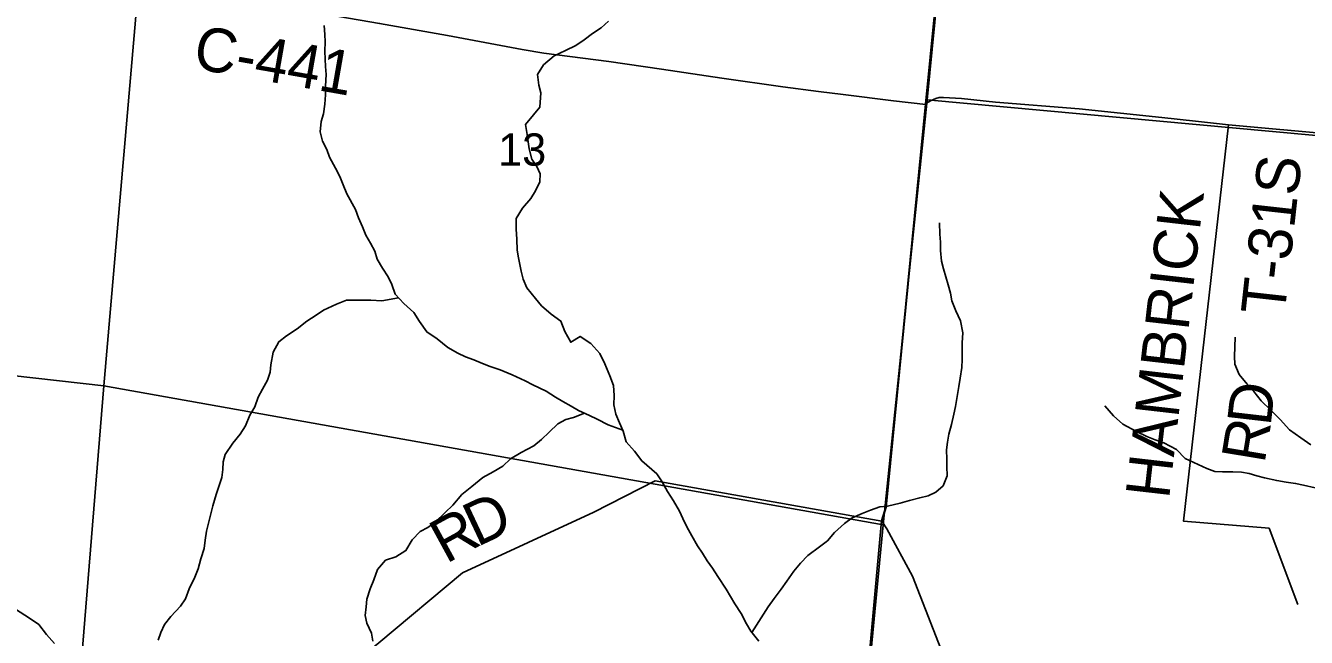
# Model space of a CAD drawing. Extents: x 0 to 42, y 0 to 22.
# Drawn here: x 4.613 to 5.443, y 17.925 to 18.322 of the extents above; entities that cross this region are included whole.
import ezdxf

# ---------------------------------------------------------------- set-up
doc = ezdxf.new("R2010")
doc.units = 0
for name, color, linetype in [('GM_X_County_Road', 7, 'Continuous'), ('GM_X_County_Road_Text', 7, 'Continuous'), ('GM_X_Minor_River', 7, 'Continuous'), ('GM_X_Section', 7, 'Continuous'), ('GM_X_Section_Text', 7, 'Continuous'), ('GM_X_Township', 7, 'Continuous'), ('GM_X_Township_Road', 7, 'Continuous'), ('GM_X_Township_Road_Text', 7, 'Continuous')]:
    doc.layers.add(name, color=color, linetype=linetype)

msp = doc.modelspace()

# ---------------------------------------------------------------- linework, layer by layer
at = {"layer": 'GM_X_County_Road'}
for points in [[(4.81578, 18.32783), (4.84215, 18.32344), (4.88614, 18.31567), (4.93448, 18.30655), (4.94854, 18.30422), (4.99075, 18.29864), (5.0248, 18.29385), (5.0639, 18.28795), (5.10334, 18.28236), (5.1266, 18.27937), (5.14248, 18.27731), (5.17514, 18.27319), (5.19606, 18.27082)], [(4.63561, 17.80179), (4.69832, 17.82776), (4.72485, 17.83901), (4.75732, 17.85441), (4.77317, 17.86587), (4.84161, 17.92186), (4.89586, 17.96725), (4.98086, 18.00667), (5.02064, 18.02691), (5.16751, 18.00075), (5.1704, 18.00991), (5.19606, 18.27082)], [(5.19606, 18.27082), (5.1977, 18.27238), (5.19967, 18.27352), (5.20249, 18.27481), (5.20484, 18.27535), (5.20745, 18.27548), (5.21927, 18.27469), (5.24122, 18.27246), (5.29542, 18.26803), (5.34906, 18.2624)], [(5.34906, 18.2624), (5.37091, 18.26011), (5.39234, 18.25778), (5.59722, 18.2391)]]:
    msp.add_lwpolyline(points, dxfattribs=at)
at = {"layer": 'GM_X_Minor_River'}
for points in [[(4.99971, 18.05981), (4.99035, 18.06327), (4.98319, 18.0669), (4.9781, 18.06939), (4.97112, 18.07245), (4.96622, 18.07531), (4.96094, 18.07837), (4.95604, 18.08123), (4.95001, 18.08505), (4.94134, 18.08926), (4.93643, 18.09174), (4.92814, 18.09576), (4.92021, 18.09883), (4.9138, 18.10113), (4.9089, 18.10305), (4.90324, 18.10535), (4.89777, 18.10727), (4.89286, 18.10975), (4.88627, 18.11338), (4.87949, 18.11891), (4.87271, 18.12349), (4.86801, 18.13014), (4.86426, 18.13603), (4.85786, 18.14194), (4.85221, 18.14784), (4.85016, 18.1541), (4.84773, 18.15923), (4.84397, 18.16474), (4.8406, 18.17063), (4.83911, 18.17576), (4.8363, 18.18108), (4.8333, 18.18621), (4.83105, 18.19152), (4.82843, 18.19741), (4.82657, 18.20273), (4.82094, 18.21299), (4.81851, 18.21887), (4.81627, 18.22419), (4.81364, 18.22951), (4.80971, 18.23673), (4.80803, 18.24166), (4.80522, 18.24717), (4.80373, 18.25305), (4.80433, 18.25988), (4.80586, 18.2648), (4.80664, 18.27105), (4.80705, 18.27711), (4.80707, 18.2828), (4.80748, 18.29038), (4.80713, 18.2955), (4.80677, 18.30024), (4.8066, 18.30535), (4.80682, 18.31142), (4.80665, 18.31616), (4.8063, 18.32204)], [(5.08781, 17.92296), (5.08274, 17.92943), (5.07992, 17.93437), (5.07636, 17.94102), (5.07242, 17.94729), (5.06679, 17.9568), (5.06135, 17.96497), (5.05797, 17.97029), (5.0544, 17.97504), (5.0514, 17.97998), (5.04821, 17.98474), (5.04446, 17.99139), (5.04127, 17.99709), (5.03865, 18.0026), (5.0364, 18.00734), (5.03265, 18.01399), (5.02871, 18.02008), (5.02515, 18.02635), (5.02177, 18.03148), (5.01198, 18.03986), (5.00728, 18.04614), (5.00202, 18.05222), (4.99997, 18.05925), (4.99754, 18.06456), (4.99529, 18.07007), (4.994, 18.07614), (4.99421, 18.0822), (4.99367, 18.08884), (4.99143, 18.09511), (4.98807, 18.1027), (4.98488, 18.10954), (4.97905, 18.11601), (4.97208, 18.12059), (4.96602, 18.11682), (4.96208, 18.12385), (4.95966, 18.1305), (4.95325, 18.13507), (4.94704, 18.14041), (4.94309, 18.14516), (4.93764, 18.15201), (4.93521, 18.15771), (4.93391, 18.16283), (4.93206, 18.17156), (4.93132, 18.17649), (4.93097, 18.1835), (4.93062, 18.19014), (4.93066, 18.19696), (4.93465, 18.20377), (4.94016, 18.21), (4.9432, 18.21491), (4.94606, 18.22078), (4.94609, 18.2259), (4.94403, 18.23064), (4.94084, 18.23539), (4.93898, 18.24204), (4.93843, 18.24678), (4.93769, 18.25152), (4.93678, 18.25797), (4.94191, 18.2642), (4.94589, 18.26911), (4.94669, 18.27839), (4.94539, 18.28333), (4.94447, 18.29035), (4.94828, 18.29658), (4.9553, 18.30243), (4.96268, 18.30581), (4.96931, 18.30919), (4.9748, 18.31277), (4.98011, 18.31692), (4.9858, 18.32049), (4.99054, 18.32483)], [(5.08342, 17.92856), (5.09395, 17.9453), (5.09775, 17.95059), (5.10232, 17.95683), (5.10593, 17.96193), (5.11049, 17.96836), (5.11486, 17.97364), (5.1196, 17.97855), (5.12719, 17.9842), (5.1323, 17.98816), (5.13686, 17.99345), (5.14331, 17.9993), (5.14843, 18.00307), (5.15487, 18.00588), (5.16017, 18.00794), (5.16622, 18.01), (5.17132, 18.01055), (5.17946, 18.01241), (5.18551, 18.01428), (5.19213, 18.01595), (5.19762, 18.01726), (5.20254, 18.0197), (5.20728, 18.02366), (5.20995, 18.03009), (5.20979, 18.03616), (5.20981, 18.0409), (5.20946, 18.04696), (5.21005, 18.05208), (5.21102, 18.05719), (5.21274, 18.06344), (5.21428, 18.07007), (5.21525, 18.07518), (5.21757, 18.08806), (5.21835, 18.09355), (5.21933, 18.10037), (5.21973, 18.10568), (5.21956, 18.11098), (5.21959, 18.11648), (5.21999, 18.12292), (5.21852, 18.1307), (5.21552, 18.13716), (5.2129, 18.14361), (5.21217, 18.14855), (5.21049, 18.15405), (5.20751, 18.1643), (5.20621, 18.16923), (5.20567, 18.17625), (5.2057, 18.18155), (5.20515, 18.18686), (5.205, 18.19426)], [(4.85437, 18.14558), (4.84351, 18.14371), (4.83652, 18.14412), (4.83123, 18.14414), (4.82593, 18.14397), (4.82064, 18.14399), (4.81421, 18.14156), (4.80569, 18.13762), (4.80095, 18.13423), (4.79507, 18.13046), (4.78863, 18.12556), (4.78181, 18.12085), (4.77688, 18.11709), (4.77307, 18.11028), (4.77171, 18.10214), (4.77112, 18.0974), (4.7694, 18.0921), (4.76616, 18.08643), (4.76349, 18.08113), (4.76139, 18.07489), (4.75796, 18.06941), (4.75529, 18.06259), (4.75186, 18.0573), (4.74711, 18.05126), (4.74217, 18.04408), (4.74083, 18.03916), (4.74061, 18.03423), (4.73984, 18.02911), (4.73792, 18.02325), (4.7362, 18.01814), (4.73409, 18.01076), (4.73216, 18.00299), (4.73005, 17.99428), (4.72908, 17.9886), (4.72849, 17.98311), (4.72619, 17.97648), (4.72465, 17.96986), (4.72236, 17.96456), (4.71874, 17.95699), (4.71644, 17.95056), (4.71302, 17.94565), (4.70694, 17.93904), (4.70277, 17.93394), (4.70029, 17.92865), (4.69875, 17.92373)], [(5.44567, 18.05029), (5.43907, 18.05486), (5.43173, 18.06001), (5.42571, 18.06667), (5.41969, 18.07277), (5.41348, 18.07886), (5.40859, 18.08495), (5.40427, 18.0897), (5.39919, 18.09598), (5.39639, 18.10263), (5.39603, 18.10756), (5.39644, 18.11381), (5.39665, 18.12007)], [(4.97501, 18.07074), (4.9677, 18.06792), (4.96278, 18.0668), (4.95767, 18.06398), (4.95197, 18.05851), (4.94704, 18.05379), (4.94211, 18.04964), (4.93397, 18.04532), (4.92696, 18.04118), (4.92202, 18.03646), (4.91577, 18.0327), (4.90914, 18.02913), (4.90194, 18.02328), (4.89549, 18.018), (4.8896, 18.01121), (4.88467, 18.00649), (4.87822, 18.00007), (4.87348, 17.99668), (4.86837, 17.99405), (4.86324, 17.98877), (4.85924, 17.98177), (4.85261, 17.97763), (4.84599, 17.97558), (4.84086, 17.96953), (4.83837, 17.96272), (4.83608, 17.95704), (4.83397, 17.95023), (4.83339, 17.94531), (4.83279, 17.93962), (4.83391, 17.93469), (4.8369, 17.92823), (4.83782, 17.92311)], [(5.44838, 18.02241), (5.44083, 18.02415), (5.43574, 18.02531), (5.42969, 18.02609), (5.42346, 18.02707), (5.41553, 18.02881), (5.41062, 18.03016), (5.40572, 18.0317), (5.40062, 18.03248), (5.39514, 18.03288), (5.38834, 18.03272), (5.38343, 18.03293), (5.37814, 18.03485), (5.36985, 18.03887), (5.36419, 18.04136), (5.35855, 18.04726), (5.35025, 18.05165), (5.34478, 18.05357), (5.33931, 18.05568), (5.33271, 18.05893), (5.32385, 18.06371), (5.31764, 18.06905), (5.312, 18.07552)], [(4.63147, 17.92156), (4.62621, 17.92746), (4.62132, 17.93374), (4.61529, 17.93793), (4.60625, 17.94385), (4.60059, 17.94558), (4.59341, 17.94732), (4.5885, 17.94753), (4.5834, 17.94736), (4.57546, 17.94683), (4.56865, 17.94553), (4.56146, 17.9431), (4.55635, 17.94142), (4.55067, 17.94012), (4.54387, 17.9392), (4.53649, 17.93848), (4.53083, 17.93869), (4.52479, 17.94099), (4.51913, 17.94272), (4.51156, 17.94124), (4.50645, 17.93785), (4.50188, 17.93162), (4.49695, 17.92728), (4.49146, 17.92408)]]:
    msp.add_lwpolyline(points, dxfattribs=at)
at = {"layer": 'GM_X_Section'}
for points in [[(5.24862, 18.78217), (5.88694, 18.72342), (5.84475, 18.21447), (5.19696, 18.27399), (5.22327, 18.54106)], [(4.20614, 18.62998), (4.70656, 18.58779), (4.66343, 18.08851), (4.15734, 18.14567)], [(4.70656, 18.58779), (5.22327, 18.54106), (5.19696, 18.27399), (5.16837, 17.9984), (4.66343, 18.08851)], [(5.84475, 18.21447), (5.80483, 17.71083), (5.14624, 17.766), (5.16837, 17.9984), (5.19696, 18.27399)], [(4.66343, 18.08851), (4.61913, 17.54396), (4.09844, 17.5892), (4.15734, 18.14567)], [(5.16837, 17.9984), (5.14624, 17.766), (5.12031, 17.49685), (4.61913, 17.54396), (4.66343, 18.08851)]]:
    msp.add_lwpolyline(points, close=True, dxfattribs=at)
at = {"layer": 'GM_X_Township'}
msp.add_lwpolyline([(5.14624, 17.76794), (5.1674, 18.00102), (5.17029, 18.01018), (5.19596, 18.27109), (5.23598, 18.67597), (5.24802, 18.79207), (5.25291, 18.82566), (5.25334, 18.82864), (5.25368, 18.83198), (5.25833, 18.87833), (5.2718, 19.04643), (5.3216, 19.54433), (5.32553, 19.6128), (5.332, 19.68245), (5.33749, 19.74156), (5.35499, 19.92984), (5.38817, 20.287), (5.7544, 20.26066), (6.25694, 20.21504), (6.30624, 20.21096), (6.44864, 20.19642)], dxfattribs=at)
at = {"layer": 'GM_X_Township_Road'}
for points in [[(5.14624, 17.76794), (5.1674, 18.00102), (5.17029, 18.01018), (5.19596, 18.27109), (5.23598, 18.67597), (5.24802, 18.79207), (5.25291, 18.82566), (5.25334, 18.82864), (5.25368, 18.83198), (5.25833, 18.87833), (5.2718, 19.04643), (5.3216, 19.54433), (4.81946, 19.58526), (4.65033, 19.6034), (4.61855, 19.6065), (4.61368, 19.60698), (4.60887, 19.60735)], [(5.39234, 18.25778), (5.36309, 18.00075), (5.41856, 17.99621), (5.43721, 17.94681)], [(5.30514, 17.62924), (5.27511, 17.6894), (5.2738, 17.69245), (5.27245, 17.69624), (5.27168, 17.6984), (5.25546, 17.74377), (5.25447, 17.74654), (5.25383, 17.75319), (5.24924, 17.80115), (5.24916, 17.80196), (5.24538, 17.80993), (5.23091, 17.84039), (5.22907, 17.84429), (5.22767, 17.84942), (5.21384, 17.90058), (5.21371, 17.90104), (5.20938, 17.90911), (5.18756, 17.96518), (5.17088, 17.99574), (5.16751, 18.00075)]]:
    msp.add_lwpolyline(points, dxfattribs=at)

# ---------------------------------------------------------------- texts
at = {"layer": 'GM_X_County_Road_Text'}
for s, height, rotation, p in [('C-441', 0.028409, 350.04014, (4.72043, 18.29445)), ('D', 0.02841, 25.19976, (4.90528, 17.98387)), ('R', 0.02841, 28.59893, (4.8852, 17.97291))]:
    msp.add_text(s, height=height, rotation=rotation, dxfattribs=at).set_placement(p)
at = {"layer": 'GM_X_Section_Text'}
msp.add_text('13', height=0.020928, rotation=0.00001, dxfattribs=at).set_placement((4.91897, 18.23122))
at = {"layer": 'GM_X_Township_Road_Text'}
for s, height, rotation, p in [('T-31S', 0.028409, 83.66003, (5.42844, 18.13345)), ('HAMBRICK', 0.028409, 83.47672, (5.3537, 18.01475)), ('D', 0.02841, 83.38054, (5.4195, 18.06195)), ('R', 0.02841, 80.65077, (5.41554, 18.03766))]:
    msp.add_text(s, height=height, rotation=rotation, dxfattribs=at).set_placement(p)

doc.saveas('drawing.dxf')
